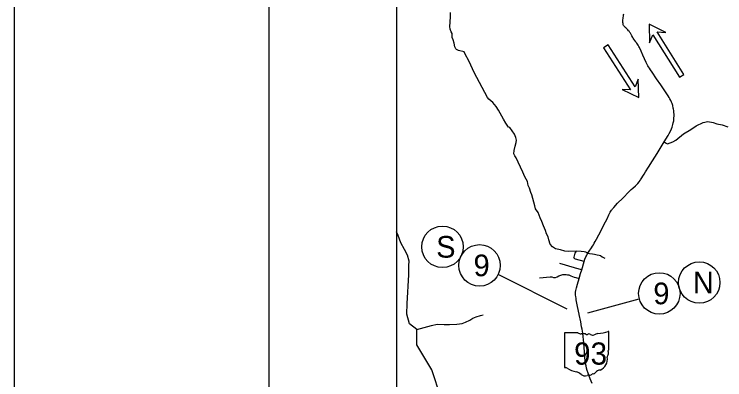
# Model space of a CAD drawing. Extents: x 2025369 to 2161369, y 549489 to 637489.
# Drawn here: x 2025369 to 2047673, y 589374 to 600839 of the extents above; entities that cross this region are included whole.
import ezdxf

# ---------------------------------------------------------------- set-up
doc = ezdxf.new("R2010")
doc.units = 0
for name, color, linetype in [('GM_X_County_Road', 7, 'Continuous'), ('GM_X_State_Route', 7, 'Continuous'), ('GM_X_State_Shield', 7, 'Continuous'), ('GM_X_Township_Road', 7, 'Continuous'), ('GM_X_Township_Subdivision', 7, 'Continuous'), ('SH_Border', 7, 'Continuous'), ('SH_Cut_Line', 7, 'Continuous'), ('SH_Text', 7, 'Continuous')]:
    doc.layers.add(name, color=color, linetype=linetype)

msp = doc.modelspace()

# ---------------------------------------------------------------- linework, layer by layer
at = {"layer": 'GM_X_County_Road'}
for points in [[(2045769, 596834), (2045831, 596791), (2045874, 596776), (2046046, 596836), (2046132, 596888), (2046378, 597083), (2046602, 597220), (2046773, 597340), (2046989, 597447), (2047145, 597475), (2047304, 597444), (2047422, 597403), (2047591, 597367), (2047773, 597306)], [(2038762, 588825), (2038480, 589681), (2038132, 590258), (2038010, 590471), (2038003, 590652), (2038005, 590948), (2037776, 591132), (2037694, 591430), (2037706, 591768), (2037760, 592670), (2037754, 592959), (2037767, 593099), (2037714, 593284), (2037619, 593455), (2037508, 593668), (2037418, 593900), (2037369, 594018)]]:
    msp.add_lwpolyline(points, dxfattribs=at)
at = {"layer": 'GM_X_State_Route'}
for points in [[(2044849, 600013), (2044817, 600055), (2044796, 600085), (2044781, 600107), (2044751, 600161), (2044729, 600203), (2044709, 600241), (2044695, 600265), (2044682, 600286), (2044668, 600305), (2044654, 600321), (2044628, 600350), (2044610, 600366), (2044588, 600386), (2044563, 600408), (2044538, 600433), (2044523, 600450), (2044508, 600470), (2044498, 600489), (2044488, 600511), (2044482, 600534), (2044478, 600554), (2044476, 600573), (2044476, 600599), (2044477, 600631), (2044485, 600737), (2044489, 600778), (2044494, 600817), (2044500, 600852)], [(2045186, 595896), (2045277, 596039), (2045407, 596246), (2045546, 596472), (2045676, 596682), (2045769, 596834), (2045897, 597038), (2045931, 597096), (2045969, 597172), (2046001, 597243), (2046022, 597301), (2046034, 597341), (2046045, 597379), (2046057, 597433), (2046069, 597495), (2046075, 597550), (2046078, 597594), (2046080, 597641), (2046079, 597698), (2046076, 597763), (2046069, 597823), (2046063, 597860), (2046057, 597893), (2046037, 597974), (2046016, 598040), (2046001, 598081), (2045975, 598138), (2045952, 598185), (2045931, 598225), (2045893, 598284), (2045829, 598375), (2045662, 598622), (2045527, 598815), (2045389, 599017), (2045339, 599092), (2045306, 599143), (2045280, 599186), (2045260, 599220), (2045237, 599264), (2045208, 599322), (2045104, 599553), (2045050, 599679), (2045006, 599774), (2044994, 599799), (2044977, 599829), (2044954, 599865), (2044933, 599897), (2044908, 599935), (2044893, 599954), (2044878, 599974), (2044849, 600013)], [(2043104, 591419), (2043101, 591432), (2043052, 591672), (2043010, 591884), (2043003, 591922), (2042994, 591983), (2042988, 592029), (2042986, 592068), (2042989, 592127), (2042995, 592177), (2043014, 592255), (2043049, 592378), (2043103, 592555), (2043146, 592704), (2043181, 592823), (2043258, 593082), (2043284, 593157), (2043313, 593226), (2043333, 593264), (2043356, 593310), (2043375, 593345), (2043411, 593405), (2043485, 593515), (2043518, 593565), (2043548, 593611), (2043574, 593654), (2043604, 593706), (2043647, 593780), (2043720, 593917), (2043780, 594033), (2043879, 594229), (2043976, 594425), (2044036, 594547), (2044058, 594589), (2044078, 594626), (2044098, 594661), (2044118, 594693), (2044133, 594713), (2044149, 594734), (2044165, 594755), (2044187, 594780), (2044310, 594912), (2044468, 595075), (2044673, 595284), (2044729, 595339), (2044783, 595388), (2044865, 595460), (2044909, 595499), (2044946, 595535), (2044982, 595578), (2045014, 595622), (2045030, 595646), (2045142, 595826), (2045186, 595896)], [(2043505, 589262), (2043446, 589406), (2043404, 589515), (2043379, 589585), (2043356, 589664), (2043336, 589739), (2043319, 589811), (2043305, 589885), (2043282, 590077), (2043255, 590402), (2043234, 590641), (2043227, 590723), (2043214, 590834), (2043195, 590958), (2043180, 591035), (2043149, 591192), (2043104, 591419)]]:
    msp.add_lwpolyline(points, dxfattribs=at)
at = {"layer": 'GM_X_State_Shield'}
for p, q in [((2042641, 590831), (2042641, 589775)), ((2043063, 590850), (2042655, 590850)), ((2044034, 590323), (2044034, 590876)), ((2044033, 590323), (2044034, 590323))]:
    msp.add_line(p, q, dxfattribs=at)
for centre, radius, start, end in [((2042657, 590834), 16.1, 98.1301, 188.1301), ((2043160, 590972), 156, 231.6195, 271.1119), ((2043538, 592290), 1476, 275.8445, 288.9065), ((2044018, 590878), 15.5, 351.8621, 97.738), ((2043212, 590256), 562, 80.4867, 94.9883), ((2043339, 590839), 45.1, 219.7921, 297.1024), ((2043405, 590717), 93.8, 54.4667, 119.1411), ((2043527, 590885), 113, 233.8562, 294.8282), ((2043726, 590527), 297, 97.3462, 120.7689), ((2044089, 590092), 105, 136.8065, 186.9296), ((2044030, 590282), 24, 107.944, 210.337), ((2043877, 590213), 144, 340.033, 23.6496), ((2044017, 590321), 16.6, 289.6038, 7.7341), ((2043620, 590021), 369, 292.3089, 8.9858), ((2042657, 589772), 16.3, 171.9584, 258.3066), ((2042660, 589881), 124, 267.339, 280.6039), ((2042685, 589714), 44.8, 29.7484, 93.2717), ((2043251, 590663), 1066, 240.4129, 257.1985), ((2042933, 589300), 334, 47.1842, 75.836), ((2043294, 589709), 212, 230.7004, 286.2918), ((2043416, 589343), 174, 85.6951, 111.2099), ((2043431, 589629), 113, 268.777, 315.5493), ((2043533, 589527), 31.8, 65.7517, 132.6484), ((2043520, 589672), 119, 282.8732, 323.2771), ((2043776, 589478), 202, 94.4031, 142.5768)]:
    msp.add_arc(centre, radius, start, end, dxfattribs=at)
at = {"layer": 'GM_X_Township_Road'}
for points in [[(2039112, 600232), (2039085, 600285), (2039052, 600365), (2039040, 600457), (2039050, 600594), (2039062, 600772), (2039068, 600894)], [(2043375, 593345), (2043315, 593374), (2043257, 593390), (2043168, 593398), (2043013, 593413), (2042770, 593398), (2042656, 593406), (2042515, 593446), (2042354, 593477), (2042263, 593541), (2042195, 593632), (2042145, 593763), (2042125, 593859), (2042078, 593948), (2042040, 594055), (2041985, 594200), (2041925, 594337), (2041881, 594452), (2041816, 594623), (2041732, 594733), (2041705, 594827), (2041612, 595179), (2041585, 595250), (2041539, 595387), (2041502, 595467), (2041477, 595596), (2041393, 595737), (2041336, 595882), (2041187, 596203), (2041126, 596336), (2041087, 596395), (2041050, 596460), (2041066, 596570), (2041098, 596705), (2041122, 596821), (2041133, 596891), (2041112, 596969), (2041070, 597074), (2040998, 597179), (2040924, 597287), (2040880, 597301), (2040798, 597425), (2040730, 597548), (2040566, 597835), (2040496, 597949), (2040390, 598070), (2040266, 598172), (2040227, 598227), (2039801, 599015), (2039646, 599352), (2039515, 599606), (2039488, 599659), (2039313, 599706), (2039271, 599720), (2039251, 599735), (2039228, 599757), (2039199, 599814), (2039173, 599928), (2039149, 600035), (2039116, 600109), (2039120, 600216), (2039112, 600232)], [(2043375, 593345), (2043427, 593339), (2043522, 593327), (2043578, 593313), (2043628, 593300), (2043670, 593292), (2043732, 593281), (2043776, 593269), (2043821, 593229), (2043908, 593185)], [(2041860, 592567), (2042192, 592606), (2042241, 592599), (2042300, 592585), (2042355, 592580), (2042408, 592599), (2042466, 592637), (2042523, 592659), (2042593, 592679), (2042653, 592675), (2042697, 592673), (2042738, 592667), (2042776, 592662), (2042843, 592634), (2042944, 592593), (2042997, 592587), (2043103, 592555)], [(2038005, 590948), (2038463, 591076), (2038647, 591120), (2038860, 591110), (2039032, 591105), (2039260, 591120), (2039433, 591140), (2039539, 591186), (2039666, 591247), (2039768, 591308), (2039869, 591348), (2040006, 591389), (2040088, 591410)]]:
    msp.add_lwpolyline(points, dxfattribs=at)
at = {"layer": 'GM_X_Township_Subdivision'}
for points in [[(2043258, 593082), (2042982, 593161), (2042968, 593165), (2042938, 593194), (2042941, 593216), (2042956, 593265), (2042981, 593340), (2043013, 593413)], [(2042984, 592879), (2042956, 592888), (2042493, 593025)], [(2043181, 592823), (2042984, 592879)]]:
    msp.add_lwpolyline(points, dxfattribs=at)
at = {"layer": 'SH_Border'}
msp.add_lwpolyline([(2033369, 635489), (2159369, 635489), (2159369, 551489), (2033369, 551489)], close=True, dxfattribs=at)
at = {"layer": 'SH_Cut_Line'}
msp.add_lwpolyline([(2025369, 549489), (2161369, 549489), (2161369, 637489), (2025369, 637489)], close=True, dxfattribs=at)
at = {"layer": 'SH_Text'}
for p, q in [((2042723, 591594), (2040556, 592672)), ((2043370, 591472), (2044990, 591912))]:
    msp.add_line(p, q, dxfattribs=at)
msp.add_lwpolyline([(2037369, 631489), (2037369, 571561), (2092420, 571561), (2092420, 631489)], dxfattribs=at)
for points in [[(2046246, 598863), (2046387, 598952), (2045554, 600283), (2045822, 600264), (2045302, 600529), (2045313, 599946), (2045413, 600195)], [(2044009, 599879), (2043870, 599789), (2044718, 598467), (2044450, 598483), (2044973, 598224), (2044955, 598807), (2044858, 598557)]]:
    msp.add_lwpolyline(points, close=True, dxfattribs=at)
for centre in [(2038812, 593544), (2039974, 592962), (2046872, 592423), (2045617, 592083)]:
    msp.add_circle(centre, 650, dxfattribs=at)

# ---------------------------------------------------------------- texts
at = {"layer": 'GM_X_State_Shield'}
msp.add_text('93', height=696.1, dxfattribs=at).set_placement((2042942, 589849))
at = {"layer": 'SH_Text'}
for s, p in [('S', (2038614, 593204)), ('9', (2039787, 592622)), ('N', (2046671, 592083)), ('9', (2045430, 591743))]:
    msp.add_text(s, height=680, dxfattribs=at).set_placement(p)

doc.saveas('drawing.dxf')
